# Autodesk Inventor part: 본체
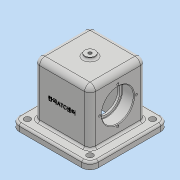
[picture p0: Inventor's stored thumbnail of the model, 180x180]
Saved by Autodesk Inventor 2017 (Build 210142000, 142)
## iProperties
Part Number: 본체
Material: 일반
Document SubType Name: Modeling
Designer: MRC
Density: 1 g/cm^3
Appearance: 기본값
Author: MRC
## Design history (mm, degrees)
sketch "스케치1"
  geometry: L1 (-58, -58)-(58, -58); L2 (58, -58)-(58, 58); L3 (58, 58)-(-58, 58); L4 (-58, 58)-(-58, -58); L5 (-58, -58)-(58, 58); L6 (58, -58)-(-58, 58); 1 further point
  constraints: 12 end point, 2 midpoint, 2 parallel, 1 horizontal, 1 perpendicular
  dimensions: "d0" = 116 distance of L3.end L2.end; "d1" = 116 distance of L2.end L1.end
extrude "돌출1" new body sketch "스케치1" distance "d2" = 10; taper "d3" = 0 deg
fillet "모깎기1" dims "d4" = 12
fillet "모깎기2" dims "d5" = 12
fillet "모깎기3" dims "d6" = 3
sketch "스케치2"
  geometry: A1 r 12 centre (-46, 46) between (-46, 58) and (-58, 46) reference; A2 r 12 centre (46, 46) between (58, 46) and (46, 58) reference; A3 r 12 centre (-46, -46) between (-58, -46) and (-46, -58) reference; A4 r 12 centre (46, -46) between (46, -58) and (58, -46) reference; 5 further points
  constraints: 4 coincident
hole "구멍1" sketch "스케치2" at (-46, 46), (46, 46), (-46, -46), (46, -46) diameter "d7" = 9; stored, may be unused: countersink angle "d11" = 90 deg, drill point angle "d13" = 0 deg; dims "d8" = 6, "d9" = 4, "d10" = 2, "d12" = 8
sketch "스케치3"
  geometry: L1 (-41, 41)-(41, 41); L2 (41, 41)-(41, -41); L3 (41, -41)-(-41, -41); L4 (-41, -41)-(-41, 41); L5 (-41, 41)-(41, -41); L6 (41, 41)-(-41, -41); 1 further point
  constraints: 12 end point, 2 midpoint, 2 parallel, 1 horizontal, 1 perpendicular
  dimensions: "d14" = 82 distance of L2.end L3.end; "d15" = 82 distance of L1.end L2.end
extrude "돌출2" join sketch "스케치3" distance "d16" = 80; taper "d17" = 0 deg
fillet "모깎기4" dims "d18" = 8
fillet "모깎기5" dims "d19" = 8
fillet "모깎기6" dims "d20" = 3
sketch "스케치4"
  geometry: C1 r 7.5 at (0, 0); 1 further point
  constraints: 1 centre point, 1 coincident
  dimensions: "d21" = 15 diameter of C1
extrude "돌출3" join sketch "스케치4" distance "d22" = 4; taper "d23" = 0 deg
sketch "스케치6"
  geometry: L1 (21, -30)-(-21, -30); L2 (-21, -30)-(-21, 30); L3 (-21, 30)-(21, 30); L4 (21, 30)-(21, -30); L5 (-21, -30)-(21, 30); 2 further points
  constraints: 10 end point, 2 parallel, 1 horizontal, 1 midpoint, 1 perpendicular
  dimensions: "d24" = 42 distance of L2.end L3.end; "d25" = 60 distance of L1.end L2.end
extrude "돌출4" cut sketch "스케치6" distance "d26" = 80; taper "d27" = 0 deg
fillet "모깎기7" dims "d28" = 3
sketch "스케치7"
  geometry: 2 further points
  constraints: 1 coincident
hole "구멍2" sketch "스케치7" at (0, 0) diameter "d29" = 4.917; stored, may be unused: countersink angle "d33" = 90 deg, drill point angle "d35" = 0 deg; dims "d30" = 12, "d31" = 4, "d32" = 2, "d34" = 77.1
sketch "스케치12"
  geometry: L1 (-82, 33)-(12, 33); L2 (12, 25.5)-(12, 40.5) reference; L3 (-82, 79)-(-82, -13) reference; C1 r 20 at (-34, 33)
  constraints: 2 end point, 1 centre point, 1 midpoint, 1 point on line
  dimensions: "d47" = 40 diameter of C1; "d48" = 48 distance from line of L3 C1.centre
extrude "돌출8" cut sketch "스케치12" stored distance "d49" = 17; taper "d50" = 0 deg
sketch "스케치13"
  geometry: C1 r 20 at (-34, 33) reference; C2 r 23.5 at (-34, 33); 1 further point
  constraints: 1 centre point, 1 coincident
  dimensions: "d51" = 47 diameter of C2
extrude "돌출9" cut sketch "스케치13" distance "d52" = 17; taper "d53" = 0 deg
fillet "모깎기8" dims "d54" = 0.6
chamfer "모따기1" distance "d55" = 1; stored, may be unused: second distance "d56" = 2, angle "d57" = 45 deg
sketch "스케치14"
  geometry: L1 (-34, 33)-(-7, 33); L2 (-34, 33)-(-34, 6); L3 (-5, 60)-(-82, 60) reference; C1 r 24.5 at (-34, 33) reference; A1 r 27 centre (-34, 33) between (-7, 33) and (-34, 6); 5 further points
  constraints: 4 end point, 4 point on circle, 3 coincident, 1 centre point, 1 point on line, 1 vertical
  dimensions: "d58" = 54 diameter of A1
hole "구멍3" sketch "스케치14" at (-7, 33), (-34, 6), (-61, 33), (-34, 60) diameter "d59" = 3.242; stored, may be unused: countersink angle "d63" = 90 deg, drill point angle "d65" = 118 deg; dims "d60" = 8, "d61" = 4, "d62" = 2, "d64" = 10
sketch "스케치15"
  geometry: L1 (-13, -82)-(79, -82) reference; L2 (33, -82)-(33, 14); 2 further points
  constraints: 2 end point, 1 coincident, 1 midpoint, 1 vertical, 1 other
  dimensions: "d66" = 48 distance from line of point (33, -34) L1
feature "엠보싱1" sketch "스케치15" dims "d0" = 116, "d1" = 116, "d67" = 0.5, "d68" = 0
fillet "모깎기9" dims "d69" = 3
node "솔리드1"
mirror "미러1"
mirror "미러2"
